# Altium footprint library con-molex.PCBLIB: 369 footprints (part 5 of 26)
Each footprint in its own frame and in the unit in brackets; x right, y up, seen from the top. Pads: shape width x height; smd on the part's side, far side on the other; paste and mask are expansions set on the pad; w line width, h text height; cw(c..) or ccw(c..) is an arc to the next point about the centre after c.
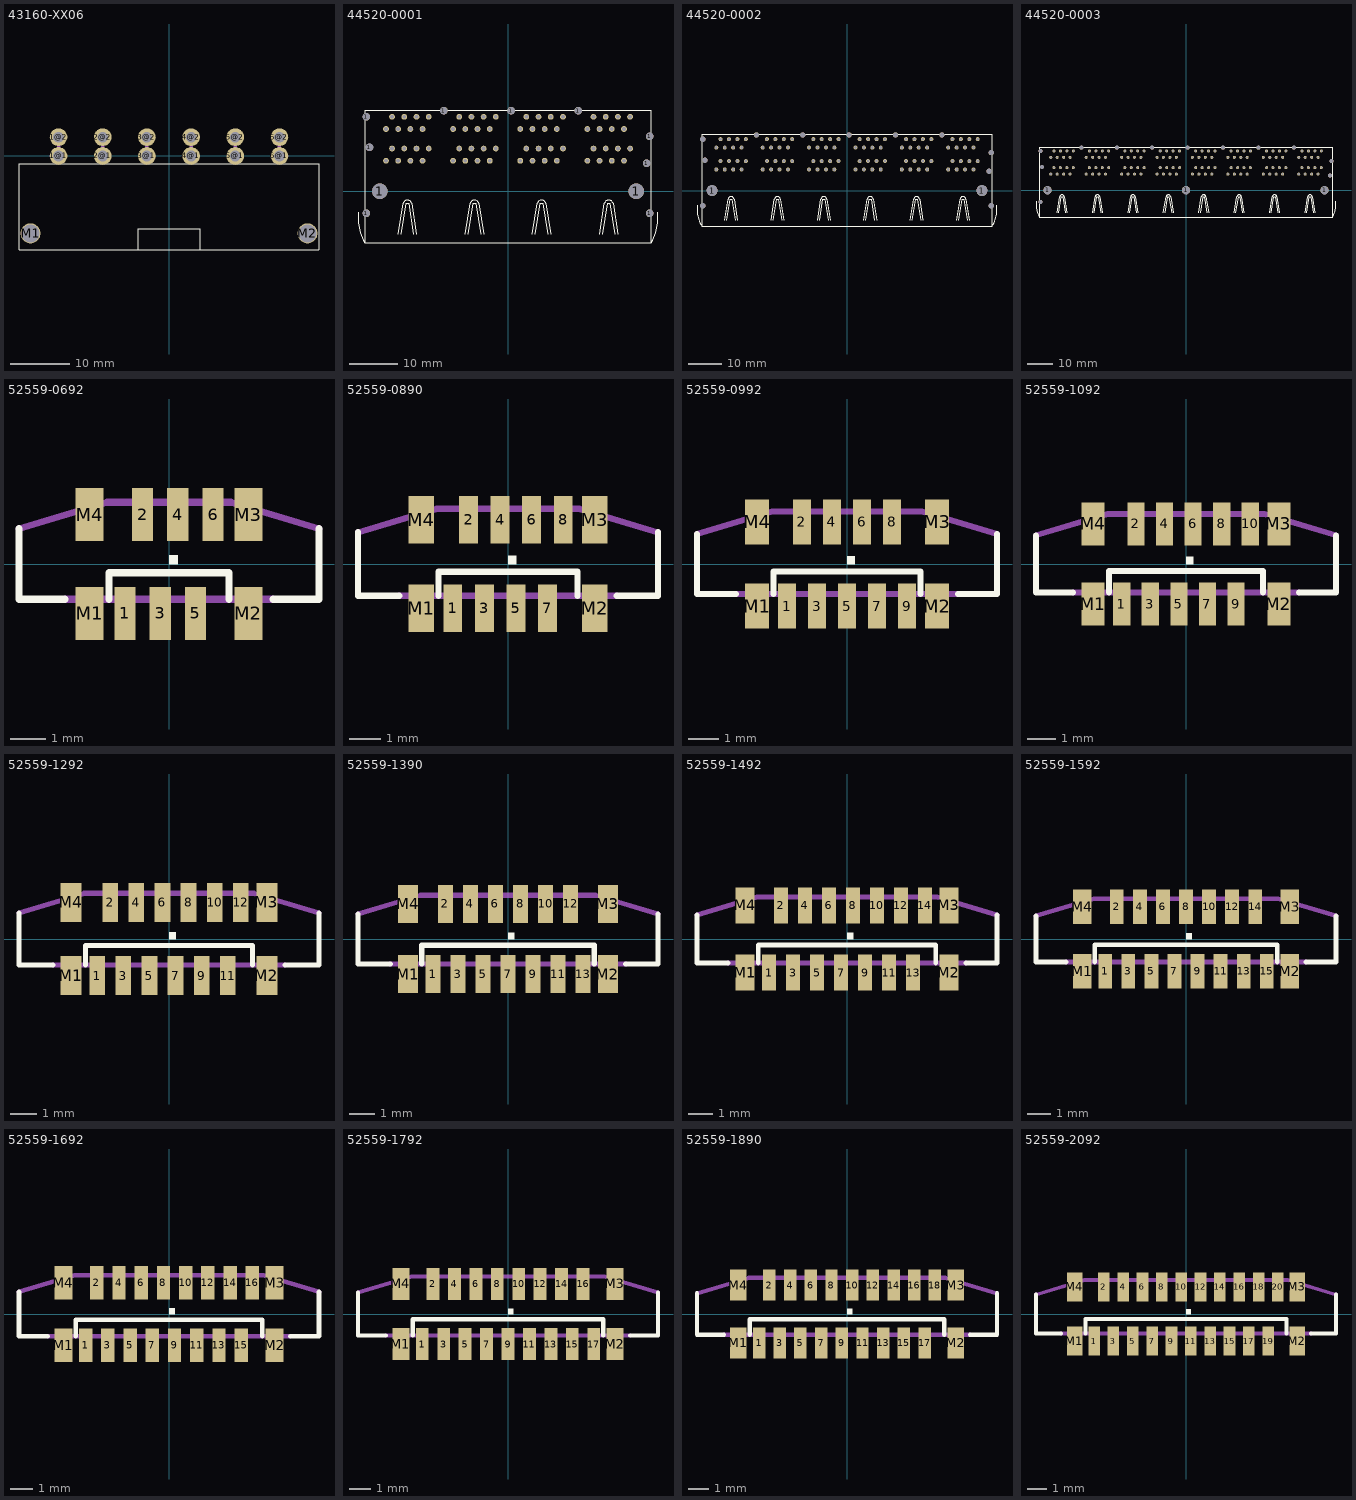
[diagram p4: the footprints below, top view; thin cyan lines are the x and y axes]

## 43160-XX06 [mm]
pads (14):
  round 3 hole 1.8: 1@1(-18.725,0) 1@2(-18.725,3.18) 2@1(-11.235,0) 2@2(-11.235,3.18) 3@1(-3.745,0) 3@2(-3.745,3.18) 4@1(3.745,0) 4@2(3.745,3.18) 5@1(11.235,0) 5@2(11.235,3.18) 6@1(18.725,0) 6@2(18.725,3.18)
  round 3.4 hole 3: M1(-23.475,-13.13) M2(23.475,-13.13)
Top Overlay:
  lines w0.203: -5.175,-15.8 -5.175,-12.325 5.175,-12.325 5.175,-15.85 ; -25.425,-15.885 -25.425,-1.325 25.425,-1.325 25.425,-15.885 -25.425,-15.885
Mechanical 16:
  lines w0.6: -18.725,-1.1 -18.725,3.745 ; -11.235,-1.1 -11.235,3.745 ; -3.745,-1.1 -3.745,3.745 ; 3.745,-1.1 3.745,3.745 ; 11.235,-1.1 11.235,3.745 ; 18.725,-1.1 18.725,3.745

## 44520-0001 [mil]
pads (75):
  round 62 hole 62: 1(-1160,-180) 1(-1160,610) 1(-1135,360) 1(-525,660) 1(25,660) 1(575,660) 1(1135,230) 1(1160,-180) 1(1160,450)
  round 128 hole 128: 1(-1050,0) 1(1050,0)
  round 47.25 hole 31.5: A1-1(-1000,250) A1-2(-950,350) A1-3(-900,250) A1-4(-850,350) A1-5(-800,250) A1-6(-750,350) A1-7(-700,250) A1-8(-650,350) A2-1(-650,610) A2-2(-700,510) A2-3(-750,610) A2-4(-800,510) A2-5(-850,610) A2-6(-900,510) A2-7(-950,610) A2-8(-1000,510) B1-1(-450,250) B1-2(-400,350) B1-3(-350,250) B1-4(-300,350) B1-5(-250,250) B1-6(-200,350) B1-7(-150,250) B1-8(-100,350) B2-1(-100,610) B2-2(-150,510) B2-3(-200,610) B2-4(-250,510) B2-5(-300,610) B2-6(-350,510) B2-7(-400,610) B2-8(-450,510) C1-1(100,250) C1-2(150,350) C1-3(200,250) C1-4(250,350) C1-5(300,250) C1-6(350,350) C1-7(400,250) C1-8(450,350) C2-1(450,610) C2-2(400,510) C2-3(350,610) C2-4(300,510) C2-5(250,610) C2-6(200,510) C2-7(150,610) C2-8(100,510) D1-1(650,250) D1-2(700,350) D1-3(750,250) D1-4(800,350) D1-5(850,250) D1-6(900,350) D1-7(950,250) D1-8(1000,350) D2-1(1000,610) D2-2(950,510) D2-3(900,610) D2-4(850,510) D2-5(800,610) D2-6(750,510) D2-7(700,610) D2-8(650,510)
Top Overlay:
  lines w8: -1227,-172 ccw(c-805.94,-213.16) -1175,-420 ; -900,-350 -860,-100 cw(c-825,-107.06) -790,-100 -750,-350 ; -875,-350 -835,-100 -815,-100 -775,-350 ; -350,-350 -310,-100 cw(c-275,-107.06) -240,-100 -200,-350 ; -325,-350 -285,-100 -265,-100 -225,-350 ; 200,-350 240,-100 cw(c275,-107.06) 310,-100 350,-350 ; 225,-350 265,-100 285,-100 325,-350 ; 750,-350 790,-100 cw(c825,-107.06) 860,-100 900,-350 ; 775,-350 815,-100 835,-100 875,-350 ; 1227,-172 cw(c783.5,-208.46) 1175,-420 ; -1175,-420 1175,-420 ; -1175,-420 -1175,660 1175,660 1175,-420

## 44520-0002 [mil]
pads (109):
  round 62 hole 62: 1(-1710,-180) 1(-1710,610) 1(-1685,360) 1(-1075,660) 1(-525,660) 1(25,660) 1(575,660) 1(1125,660) 1(1685,230) 1(1710,-180) 1(1710,450)
  round 128 hole 128: 1(-1600,0) 1(1600,0)
  round 47.25 hole 31.5: A1-1(-1550,250) A1-2(-1500,350) A1-3(-1450,250) A1-4(-1400,350) A1-5(-1350,250) A1-6(-1300,350) A1-7(-1250,250) A1-8(-1200,350) A2-1(-1200,610) A2-2(-1250,510) A2-3(-1300,610) A2-4(-1350,510) A2-5(-1400,610) A2-6(-1450,510) A2-7(-1500,610) A2-8(-1550,510) B1-1(-1000,250) B1-2(-950,350) B1-3(-900,250) B1-4(-850,350) B1-5(-800,250) B1-6(-750,350) B1-7(-700,250) B1-8(-650,350) B2-1(-650,610) B2-2(-700,510) B2-3(-750,610) B2-4(-800,510) B2-5(-850,610) B2-6(-900,510) B2-7(-950,610) B2-8(-1000,510) C1-1(-450,250) C1-2(-400,350) C1-3(-350,250) C1-4(-300,350) C1-5(-250,250) C1-6(-200,350) C1-7(-150,250) C1-8(-100,350) C2-1(-100,610) C2-2(-150,510) C2-3(-200,610) C2-4(-250,510) C2-5(-300,610) C2-6(-350,510) C2-7(-400,610) C2-8(-450,510) D1-1(100,250) D1-2(150,350) D1-3(200,250) D1-4(250,350) D1-5(300,250) D1-6(350,350) D1-7(400,250) D1-8(450,350) D2-1(450,610) D2-2(400,510) D2-3(350,610) D2-4(300,510) D2-5(250,610) D2-6(200,510) D2-7(150,610) D2-8(100,510) E1-1(650,250) E1-2(700,350) E1-3(750,250) E1-4(800,350) E1-5(850,250) E1-6(900,350) E1-7(950,250) E1-8(1000,350) E2-1(1000,610) E2-2(950,510) E2-3(900,610) E2-4(850,510) E2-5(800,610) E2-6(750,510) E2-7(700,610) E2-8(650,510) F1-1(1200,250) F1-2(1250,350) F1-3(1300,250) F1-4(1350,350) F1-5(1400,250) F1-6(1450,350) F1-7(1500,250) F1-8(1550,350) F2-1(1500,510) F2-2(1550,610) F2-3(1450,610) F2-4(1400,510) F2-5(1350,610) F2-6(1300,510) F2-7(1250,610) F2-8(1200,510)
Top Overlay:
  lines w8: -1777,-172 ccw(c-1355.94,-213.16) -1725,-420 ; -1450,-350 -1410,-100 cw(c-1375,-107.06) -1340,-100 -1300,-350 ; -1425,-350 -1385,-100 -1365,-100 -1325,-350 ; -900,-350 -860,-100 cw(c-825,-107.06) -790,-100 -750,-350 ; -875,-350 -835,-100 -815,-100 -775,-350 ; -350,-350 -310,-100 cw(c-275,-107.06) -240,-100 -200,-350 ; -325,-350 -285,-100 -265,-100 -225,-350 ; 200,-350 240,-100 cw(c275,-107.06) 310,-100 350,-350 ; 225,-350 265,-100 285,-100 325,-350 ; 750,-350 790,-100 cw(c825,-107.06) 860,-100 900,-350 ; 775,-350 815,-100 835,-100 875,-350 ; 1300,-350 1340,-100 cw(c1375,-107.06) 1410,-100 1450,-350 ; 1325,-350 1365,-100 1385,-100 1425,-350 ; 1777,-172 cw(c1333.5,-208.46) 1725,-420 ; -1725,-420 1725,-420 ; -1725,-420 -1725,660 1725,660 1725,-420

## 44520-0003 [mil]
pads (143):
  round 62 hole 62: 1(-2260,-180) 1(-2260,610) 1(-2235,360) 1(-1625,660) 1(-1075,660) 1(-525,660) 1(25,660) 1(575,660) 1(1125,660) 1(1675,660) 1(2235,230) 1(2260,450)
  round 128 hole 128: 1(-2150,0) 1(0,0) 1(2150,0)
  round 47.25 hole 31.5: A1-1(-2100,250) A1-2(-2050,350) A1-3(-2000,250) A1-4(-1950,350) A1-5(-1900,250) A1-6(-1850,350) A1-7(-1800,250) A1-8(-1750,350) A2-1(-1750,610) A2-2(-1800,510) A2-3(-1850,610) A2-4(-1900,510) A2-5(-1950,610) A2-6(-2000,510) A2-7(-2050,610) A2-8(-2100,510) B1-1(-1550,250) B1-2(-1500,350) B1-3(-1450,250) B1-4(-1400,350) B1-5(-1350,250) B1-6(-1300,350) B1-7(-1250,250) B1-8(-1200,350) B2-1(-1200,610) B2-2(-1250,510) B2-3(-1300,610) B2-4(-1350,510) B2-5(-1400,610) B2-6(-1450,510) B2-7(-1500,610) B2-8(-1550,510) C1-1(-1000,250) C1-2(-950,350) C1-3(-900,250) C1-4(-850,350) C1-5(-800,250) C1-6(-750,350) C1-7(-700,250) C1-8(-650,350) C2-1(-650,610) C2-2(-700,510) C2-3(-750,610) C2-4(-800,510) C2-5(-850,610) C2-6(-900,510) C2-7(-950,610) C2-8(-1000,510) D1-1(-450,250) D1-2(-400,350) D1-3(-350,250) D1-4(-300,350) D1-5(-250,250) D1-6(-200,350) D1-7(-150,250) D1-8(-100,350) D2-1(-100,610) D2-2(-150,510) D2-3(-200,610) D2-4(-250,510) D2-5(-300,610) D2-6(-350,510) D2-7(-400,610) D2-8(-450,510) E1-1(100,250) E1-2(150,350) E1-3(200,250) E1-4(250,350) E1-5(300,250) E1-6(350,350) E1-7(400,250) E1-8(450,350) E2-1(450,610) E2-2(400,510) E2-3(350,610) E2-4(300,510) E2-5(250,610) E2-6(200,510) E2-7(150,610) E2-8(100,510) F1-1(650,250) F1-2(700,350) F1-3(750,250) F1-4(800,350) F1-5(850,250) F1-6(900,350) F1-7(950,250) F1-8(1000,350) F2-1(950,510) F2-2(1000,610) F2-3(900,610) F2-4(850,510) F2-5(800,610) F2-6(750,510) F2-7(700,610) F2-8(650,510) G1-1(1200,250) G1-2(1250,350) G1-3(1300,250) G1-4(1350,350) G1-5(1400,250) G1-6(1450,350) G1-7(1500,250) G1-8(1550,350) G2-1(1550,610) G2-2(1500,510) G2-3(1450,610) G2-4(1400,510) G2-5(1350,610) G2-6(1300,510) G2-7(1250,610) G2-8(1200,510) H1-1(1750,250) H1-2(1800,350) H1-3(1850,250) H1-4(1900,350) H1-5(1950,250) H1-6(2000,350) H1-7(2050,250) H1-8(2100,350) H2-1(2100,610) H2-2(2050,510) H2-3(2000,610) H2-4(1950,510) H2-5(1900,610) H2-6(1850,510) H2-7(1800,610) H2-8(1750,510)
Top Overlay:
  lines w8: -2327,-172 ccw(c-1905.94,-213.16) -2275,-420 ; -2000,-350 -1960,-100 cw(c-1925,-107.06) -1890,-100 -1850,-350 ; -1975,-350 -1935,-100 -1915,-100 -1875,-350 ; -1450,-350 -1410,-100 cw(c-1375,-107.06) -1340,-100 -1300,-350 ; -1425,-350 -1385,-100 -1365,-100 -1325,-350 ; -900,-350 -860,-100 cw(c-825,-107.06) -790,-100 -750,-350 ; -875,-350 -835,-100 -815,-100 -775,-350 ; -350,-350 -310,-100 cw(c-275,-107.06) -240,-100 -200,-350 ; -325,-350 -285,-100 -265,-100 -225,-350 ; 200,-350 240,-100 cw(c275,-107.06) 310,-100 350,-350 ; 225,-350 265,-100 285,-100 325,-350 ; 750,-350 790,-100 cw(c825,-107.06) 860,-100 900,-350 ; 775,-350 815,-100 835,-100 875,-350 ; 1300,-350 1340,-100 cw(c1375,-107.06) 1410,-100 1450,-350 ; 1325,-350 1365,-100 1385,-100 1425,-350 ; 1850,-350 1890,-100 cw(c1925,-107.06) 1960,-100 2000,-350 ; 1875,-350 1915,-100 1935,-100 1975,-350 ; 2327,-172 cw(c1883.5,-208.46) 2275,-420 ; -2275,-420 2275,-420 ; -2275,-420 -2275,660 2275,660 2275,-420

## 52559-0692 [mil]
pads (10):
  rect 23.62x59.06 smd: 1(-49.21,-55.12) 2(-29.53,55.12) 3(-9.84,-55.12) 4(9.84,55.12) 5(29.53,-55.12) 6(49.21,55.12)
  rect 31.5x59.06 smd: M1(-88.58,-55.12) M2(88.58,-55.12) M3(88.58,55.12) M4(-88.58,55.12)
Top Overlay:
  region: 0,0 10,0 10,10 0,10
  lines w8: -167.32,39.37 -167.32,-39.37 -116.14,-39.37 ; -66.93,-39.37 -66.93,-9.84 66.93,-9.84 66.93,-39.37 ; 116.14,-39.37 167.32,-39.37 167.32,39.37
Mechanical 16:
  rectangle: -98.43,-61.02 -78.74,-43.31
  rectangle: -55.12,-61.02 -43.31,-43.31
  rectangle: -15.75,-61.02 -3.94,-43.31
  rectangle: 23.62,-61.02 35.43,-43.31
  rectangle: 78.74,-61.02 98.43,-43.31
  lines w8: -167.32,39.37 -68.9,68.9 68.9,68.9 167.32,39.37 ; -116.14,-39.37 116.14,-39.37

## 52559-0890 [mil]
pads (12):
  rect 23.62x59.06 smd: 1(-68.9,-55.12) 2(-49.21,55.12) 3(-29.53,-55.12) 4(-9.84,55.12) 5(9.84,-55.12) 6(29.53,55.12) 7(49.21,-55.12) 8(68.9,55.12)
  rect 31.5x59.06 smd: M1(-108.27,-55.12) M2(108.27,-55.12) M3(108.27,55.12) M4(-108.27,55.12)
Top Overlay:
  region: 0,0 10,0 10,10 0,10
  lines w8: -187.01,39.37 -187.01,-39.37 -135.83,-39.37 ; -86.61,-39.37 -86.61,-9.84 86.61,-9.84 86.61,-39.37 ; 135.83,-39.37 187.01,-39.37 187.01,39.37
Mechanical 16:
  rectangle: -118.11,-61.02 -98.43,-43.31
  rectangle: -74.8,-61.02 -62.99,-43.31
  rectangle: -35.43,-61.02 -23.62,-43.31
  rectangle: 3.94,-61.02 15.75,-43.31
  rectangle: 98.43,-61.02 118.11,-43.31
  rectangle: 43.31,-61.02 55.12,-43.31
  lines w8: -187.01,39.37 -88.58,68.9 88.58,68.9 187.01,39.37 ; -135.83,-39.37 135.83,-39.37

## 52559-0992 [mm]
pads (13):
  rect 0.6x1.5 smd: 1(-2,-1.4) 2(-1.5,1.4) 3(-1,-1.4) 4(-0.5,1.4) 5(0,-1.4) 6(0.5,1.4) 7(1,-1.4) 8(1.5,1.4) 9(2,-1.4)
  rect 0.8x1.5 smd: M1(-3,-1.4) M2(3,-1.4) M3(3,1.4) M4(-3,1.4)
Top Overlay:
  region: 0,0 0.254,0 0.254,0.254 0,0.254
  lines w0.203: -5,1 -5,-1 -3.7,-1 ; -2.45,-1 -2.45,-0.25 2.45,-0.25 2.45,-1 ; 3.7,-1 5,-1 5,1
Mechanical 16:
  rectangle: -3.25,-1.55 -2.75,-1.1
  rectangle: -2.15,-1.55 -1.85,-1.1
  rectangle: -1.15,-1.55 -0.85,-1.1
  rectangle: -0.15,-1.55 0.15,-1.1
  rectangle: 2.75,-1.55 3.25,-1.1
  rectangle: 0.85,-1.55 1.15,-1.1
  rectangle: 1.85,-1.55 2.15,-1.1
  lines w0.203: -5,1 -2.5,1.75 2.5,1.75 5,1 ; -3.7,-1 3.7,-1

## 52559-1092 [mil]
pads (14):
  rect 23.62x59.06 smd: 1(-88.58,-55.12) 2(-68.9,55.12) 3(-49.21,-55.12) 4(-29.53,55.12) 5(-9.84,-55.12) 6(9.84,55.12) 7(29.53,-55.12) 8(49.21,55.12) 9(68.9,-55.12) 10(88.58,55.12)
  rect 31.5x59.06 smd: M1(-127.95,-55.12) M2(127.95,-55.12) M3(127.95,55.12) M4(-127.95,55.12)
Top Overlay:
  region: 0,0 10,0 10,10 0,10
  lines w8: -206.69,39.37 -206.69,-39.37 -155.51,-39.37 ; -106.3,-39.37 -106.3,-9.84 106.3,-9.84 106.3,-39.37 ; 155.51,-39.37 206.69,-39.37 206.69,39.37
Mechanical 16:
  rectangle: -137.8,-61.02 -118.11,-43.31
  rectangle: -94.49,-61.02 -82.68,-43.31
  rectangle: -55.12,-61.02 -43.31,-43.31
  rectangle: -15.75,-61.02 -3.94,-43.31
  rectangle: 118.11,-61.02 137.8,-43.31
  rectangle: 23.62,-61.02 35.43,-43.31
  rectangle: 62.99,-61.02 74.8,-43.31
  lines w8: -206.69,39.37 -108.27,68.9 108.27,68.9 206.69,39.37 ; -155.51,-39.37 155.51,-39.37

## 52559-1292 [mil]
pads (16):
  rect 23.62x59.06 smd: 1(-108.27,-55.12) 2(-88.58,55.12) 3(-68.9,-55.12) 4(-49.21,55.12) 5(-29.53,-55.12) 6(-9.84,55.12) 7(9.84,-55.12) 8(29.53,55.12) 9(49.21,-55.12) 10(68.9,55.12) 11(88.58,-55.12) 12(108.27,55.12)
  rect 31.5x59.06 smd: M1(-147.64,-55.12) M2(147.64,-55.12) M3(147.64,55.12) M4(-147.64,55.12)
Top Overlay:
  region: 0,0 10,0 10,10 0,10
  lines w8: -226.38,39.37 -226.38,-39.37 -175.2,-39.37 ; -125.98,-39.37 -125.98,-9.84 125.98,-9.84 125.98,-39.37 ; 175.2,-39.37 226.38,-39.37 226.38,39.37
Mechanical 16:
  rectangle: -157.48,-61.02 -137.8,-43.31
  rectangle: -114.17,-61.02 -102.36,-43.31
  rectangle: -74.8,-61.02 -62.99,-43.31
  rectangle: -35.43,-61.02 -23.62,-43.31
  rectangle: 137.8,-61.02 157.48,-43.31
  rectangle: 3.94,-61.02 15.75,-43.31
  rectangle: 43.31,-61.02 55.12,-43.31
  rectangle: 82.68,-61.02 94.49,-43.31
  lines w8: -226.38,39.37 -127.95,68.9 127.95,68.9 226.38,39.37 ; -175.2,-39.37 175.2,-39.37

## 52559-1390 [mm]
pads (17):
  rect 0.6x1.5 smd: 1(-3,-1.4) 2(-2.5,1.4) 3(-2,-1.4) 4(-1.5,1.4) 5(-1,-1.4) 6(-0.5,1.4) 7(0,-1.4) 8(0.5,1.4) 9(1,-1.4) 10(1.5,1.4) 11(2,-1.4) 12(2.5,1.4) 13(3,-1.4)
  rect 0.8x1.5 smd: M1(-4,-1.4) M2(4,-1.4) M3(4,1.4) M4(-4,1.4)
Top Overlay:
  region: 0,0 0.254,0 0.254,0.254 0,0.254
  lines w0.203: -6,1 -6,-1 -4.7,-1 ; -3.45,-1 -3.45,-0.25 3.45,-0.25 3.45,-1 ; 4.7,-1 6,-1 6,1
Mechanical 16:
  rectangle: -4.25,-1.55 -3.75,-1.1
  rectangle: -3.15,-1.55 -2.85,-1.1
  rectangle: -2.15,-1.55 -1.85,-1.1
  rectangle: -1.15,-1.55 -0.85,-1.1
  rectangle: 3.75,-1.55 4.25,-1.1
  rectangle: -0.15,-1.55 0.15,-1.1
  rectangle: 0.85,-1.55 1.15,-1.1
  rectangle: 1.85,-1.55 2.15,-1.1
  rectangle: 2.85,-1.55 3.15,-1.1
  lines w0.203: -6,1 -3.5,1.75 3.5,1.75 6,1 ; -4.7,-1 4.7,-1

## 52559-1492 [mil]
pads (18):
  rect 23.62x59.06 smd: 1(-127.95,-55.12) 2(-108.27,55.12) 3(-88.58,-55.12) 4(-68.9,55.12) 5(-49.21,-55.12) 6(-29.53,55.12) 7(-9.84,-55.12) 8(9.84,55.12) 9(29.53,-55.12) 10(49.21,55.12) 11(68.9,-55.12) 12(88.58,55.12) 13(108.27,-55.12) 14(127.95,55.12)
  rect 31.5x59.06 smd: M1(-167.32,-55.12) M2(167.32,-55.12) M3(167.32,55.12) M4(-167.32,55.12)
Top Overlay:
  region: 0,0 10,0 10,10 0,10
  lines w8: -246.06,39.37 -246.06,-39.37 -194.88,-39.37 ; -145.67,-39.37 -145.67,-9.84 145.67,-9.84 145.67,-39.37 ; 194.88,-39.37 246.06,-39.37 246.06,39.37
Mechanical 16:
  rectangle: -177.17,-61.02 -157.48,-43.31
  rectangle: -133.86,-61.02 -122.05,-43.31
  rectangle: -94.49,-61.02 -82.68,-43.31
  rectangle: -55.12,-61.02 -43.31,-43.31
  rectangle: 157.48,-61.02 177.17,-43.31
  rectangle: -15.75,-61.02 -3.94,-43.31
  rectangle: 23.62,-61.02 35.43,-43.31
  rectangle: 62.99,-61.02 74.8,-43.31
  rectangle: 102.36,-61.02 114.17,-43.31
  lines w8: -246.06,39.37 -147.64,68.9 147.64,68.9 246.06,39.37 ; -194.88,-39.37 194.88,-39.37

## 52559-1592 [mm]
pads (19):
  rect 0.6x1.5 smd: 1(-3.5,-1.4) 2(-3,1.4) 3(-2.5,-1.4) 4(-2,1.4) 5(-1.5,-1.4) 6(-1,1.4) 7(-0.5,-1.4) 8(0,1.4) 9(0.5,-1.4) 10(1,1.4) 11(1.5,-1.4) 12(2,1.4) 13(2.5,-1.4) 14(3,1.4) 15(3.5,-1.4)
  rect 0.8x1.5 smd: M1(-4.5,-1.4) M2(4.5,-1.4) M3(4.5,1.4) M4(-4.5,1.4)
Top Overlay:
  region: 0,0 0.254,0 0.254,0.254 0,0.254
  lines w0.203: -6.5,1 -6.5,-1 -5.2,-1 ; -3.95,-1 -3.95,-0.25 3.95,-0.25 3.95,-1 ; 5.2,-1 6.5,-1 6.5,1
Mechanical 16:
  rectangle: -4.75,-1.55 -4.25,-1.1
  rectangle: -3.65,-1.55 -3.35,-1.1
  rectangle: -2.65,-1.55 -2.35,-1.1
  rectangle: -1.65,-1.55 -1.35,-1.1
  rectangle: 4.25,-1.55 4.75,-1.1
  rectangle: -0.65,-1.55 -0.35,-1.1
  rectangle: 0.35,-1.55 0.65,-1.1
  rectangle: 1.35,-1.55 1.65,-1.1
  rectangle: 2.35,-1.55 2.65,-1.1
  rectangle: 3.35,-1.55 3.65,-1.1
  lines w0.203: -6.5,1 -4,1.75 4,1.75 6.5,1 ; -5.2,-1 5.2,-1

## 52559-1692 [mil]
pads (20):
  rect 23.62x59.06 smd: 1(-147.64,-55.12) 2(-127.95,55.12) 3(-108.27,-55.12) 4(-88.58,55.12) 5(-68.9,-55.12) 6(-49.21,55.12) 7(-29.53,-55.12) 8(-9.84,55.12) 9(9.84,-55.12) 10(29.53,55.12) 11(49.21,-55.12) 12(68.9,55.12) 13(88.58,-55.12) 14(108.27,55.12) 15(127.95,-55.12) 16(147.64,55.12)
  rect 31.5x59.06 smd: M1(-187.01,-55.12) M2(187.01,-55.12) M3(187.01,55.12) M4(-187.01,55.12)
Top Overlay:
  region: 0,0 10,0 10,10 0,10
  lines w8: -265.75,39.37 -265.75,-39.37 -214.57,-39.37 ; -165.35,-39.37 -165.35,-9.84 165.35,-9.84 165.35,-39.37 ; 214.57,-39.37 265.75,-39.37 265.75,39.37
Mechanical 16:
  rectangle: -196.85,-61.02 -177.17,-43.31
  rectangle: -153.54,-61.02 -141.73,-43.31
  rectangle: -114.17,-61.02 -102.36,-43.31
  rectangle: -74.8,-61.02 -62.99,-43.31
  rectangle: 177.17,-61.02 196.85,-43.31
  rectangle: -35.43,-61.02 -23.62,-43.31
  rectangle: 3.94,-61.02 15.75,-43.31
  rectangle: 43.31,-61.02 55.12,-43.31
  rectangle: 82.68,-61.02 94.49,-43.31
  rectangle: 122.05,-61.02 133.86,-43.31
  lines w8: -265.75,39.37 -167.32,68.9 167.32,68.9 265.75,39.37 ; -214.57,-39.37 214.57,-39.37

## 52559-1792 [mm]
pads (21):
  rect 0.6x1.5 smd: 1(-4,-1.4) 2(-3.5,1.4) 3(-3,-1.4) 4(-2.5,1.4) 5(-2,-1.4) 6(-1.5,1.4) 7(-1,-1.4) 8(-0.5,1.4) 9(0,-1.4) 10(0.5,1.4) 11(1,-1.4) 12(1.5,1.4) 13(2,-1.4) 14(2.5,1.4) 15(3,-1.4) 16(3.5,1.4) 17(4,-1.4)
  rect 0.8x1.5 smd: M1(-5,-1.4) M2(5,-1.4) M3(5,1.4) M4(-5,1.4)
Top Overlay:
  region: 0,0 0.254,0 0.254,0.254 0,0.254
  lines w0.203: -7,1 -7,-1 -5.7,-1 ; -4.45,-1 -4.45,-0.25 4.45,-0.25 4.45,-1 ; 5.7,-1 7,-1 7,1
Mechanical 16:
  rectangle: -5.25,-1.55 -4.75,-1.1
  rectangle: -4.15,-1.55 -3.85,-1.1
  rectangle: -3.15,-1.55 -2.85,-1.1
  rectangle: -2.15,-1.55 -1.85,-1.1
  rectangle: 4.75,-1.55 5.25,-1.1
  rectangle: -1.15,-1.55 -0.85,-1.1
  rectangle: -0.15,-1.55 0.15,-1.1
  rectangle: 0.85,-1.55 1.15,-1.1
  rectangle: 1.85,-1.55 2.15,-1.1
  rectangle: 2.85,-1.55 3.15,-1.1
  rectangle: 3.85,-1.55 4.15,-1.1
  lines w0.203: -7,1 -4.5,1.75 4.5,1.75 7,1 ; -5.7,-1 5.7,-1

## 52559-1890 [mil]
pads (22):
  rect 23.62x59.06 smd: 1(-167.32,-55.12) 2(-147.64,55.12) 3(-127.95,-55.12) 4(-108.27,55.12) 5(-88.58,-55.12) 6(-68.9,55.12) 7(-49.21,-55.12) 8(-29.53,55.12) 9(-9.84,-55.12) 10(9.84,55.12) 11(29.53,-55.12) 12(49.21,55.12) 13(68.9,-55.12) 14(88.58,55.12) 15(108.27,-55.12) 16(127.95,55.12) 17(147.64,-55.12) 18(167.32,55.12)
  rect 31.5x59.06 smd: M1(-206.69,-55.12) M2(206.69,-55.12) M3(206.69,55.12) M4(-206.69,55.12)
Top Overlay:
  region: 0,0 10,0 10,10 0,10
  lines w8: -285.43,39.37 -285.43,-39.37 -234.25,-39.37 ; -185.04,-39.37 -185.04,-9.84 185.04,-9.84 185.04,-39.37 ; 234.25,-39.37 285.43,-39.37 285.43,39.37
Mechanical 16:
  rectangle: -216.54,-61.02 -196.85,-43.31
  rectangle: -173.23,-61.02 -161.42,-43.31
  rectangle: -133.86,-61.02 -122.05,-43.31
  rectangle: -94.49,-61.02 -82.68,-43.31
  rectangle: 196.85,-61.02 216.54,-43.31
  rectangle: -55.12,-61.02 -43.31,-43.31
  rectangle: -15.75,-61.02 -3.94,-43.31
  rectangle: 23.62,-61.02 35.43,-43.31
  rectangle: 62.99,-61.02 74.8,-43.31
  rectangle: 102.36,-61.02 114.17,-43.31
  rectangle: 141.73,-61.02 153.54,-43.31
  lines w8: -285.43,39.37 -187.01,68.9 187.01,68.9 285.43,39.37 ; -234.25,-39.37 234.25,-39.37

## 52559-2092 [mil]
pads (24):
  rect 23.62x59.06 smd: 1(-187.01,-55.12) 2(-167.32,55.12) 3(-147.64,-55.12) 4(-127.95,55.12) 5(-108.27,-55.12) 6(-88.58,55.12) 7(-68.9,-55.12) 8(-49.21,55.12) 9(-29.53,-55.12) 10(-9.84,55.12) 11(9.84,-55.12) 12(29.53,55.12) 13(49.21,-55.12) 14(68.9,55.12) 15(88.58,-55.12) 16(108.27,55.12) 17(127.95,-55.12) 18(147.64,55.12) 19(167.32,-55.12) 20(187.01,55.12)
  rect 31.5x59.06 smd: M1(-226.38,-55.12) M2(226.38,-55.12) M3(226.38,55.12) M4(-226.38,55.12)
Top Overlay:
  region: 0,0 10,0 10,10 0,10
  lines w8: -305.12,39.37 -305.12,-39.37 -253.94,-39.37 ; -204.72,-39.37 -204.72,-9.84 204.72,-9.84 204.72,-39.37 ; 253.94,-39.37 305.12,-39.37 305.12,39.37
Mechanical 16:
  rectangle: -236.22,-61.02 -216.54,-43.31
  rectangle: -192.91,-61.02 -181.1,-43.31
  rectangle: -153.54,-61.02 -141.73,-43.31
  rectangle: -114.17,-61.02 -102.36,-43.31
  rectangle: 216.54,-61.02 236.22,-43.31
  rectangle: -74.8,-61.02 -62.99,-43.31
  rectangle: -35.43,-61.02 -23.62,-43.31
  rectangle: 3.94,-61.02 15.75,-43.31
  rectangle: 43.31,-61.02 55.12,-43.31
  rectangle: 82.68,-61.02 94.49,-43.31
  rectangle: 122.05,-61.02 133.86,-43.31
  rectangle: 161.42,-61.02 173.23,-43.31
  lines w8: -305.12,39.37 -206.69,68.9 206.69,68.9 305.12,39.37 ; -253.94,-39.37 253.94,-39.37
